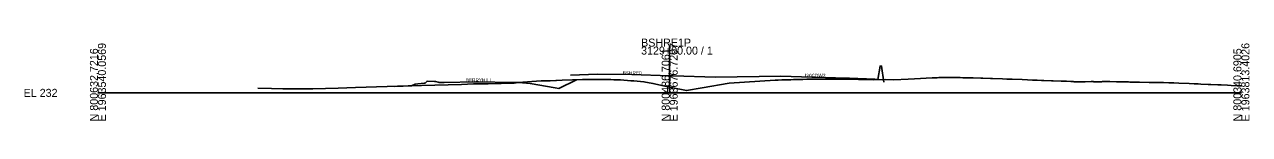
# Model space of a CAD drawing. Extents: x -26 to 403, y -10 to 6039.
# Drawn here: x -25.7 to 402.8, y 490.3 to 519 of the extents above; entities that cross this region are included whole.
import ezdxf

# ---------------------------------------------------------------- set-up
doc = ezdxf.new("R2010")
doc.units = 0
for name, color, linetype in [('Default', 7, 'Continuous'), ('RD_GPK_XS_Cell', 7, 'Continuous'), ('RD_TX_Misc1', 7, 'Continuous'), ('RD_XS_ExGround', 7, 'Continuous'), ('RD_XS_Pave', 7, 'Continuous'), ('RD_XS_TX_Elev_EX', 7, 'Continuous')]:
    doc.layers.add(name, color=color, linetype=linetype)

msp = doc.modelspace()

# ---------------------------------------------------------------- linework, layer by layer
at = {"layer": 'RD_GPK_XS_Cell'}
for p, q in [((200, 500), (200, 516.2)), ((0, 500), (200, 500)), ((200, 500), (400, 500))]:
    msp.add_line(p, q, dxfattribs=at)
at = {"layer": 'RD_XS_ExGround'}
msp.add_lwpolyline([(55.9, 501.67), (60.74, 501.51), (64.71, 501.39), (75.16, 501.41), (84.09, 501.66), (90.08, 501.85), (108.54, 502.41), (127.15, 502.96), (131.41, 503.12), (136.45, 503.18), (145.61, 503.42), (147.06, 503.59), (155.03, 504.18), (158.15, 504.26), (160.18, 504.38), (160.39, 504.38), (162.41, 504.45), (166.05, 504.54), (169.55, 504.62), (170.01, 504.62), (171.13, 504.64), (172.02, 504.64), (172.53, 504.64), (173.36, 504.64), (176.01, 504.64), (177.01, 504.64), (179.47, 504.62), (180.48, 504.61), (182, 504.58), (182.78, 504.52), (186.41, 504.24), (187.52, 504.15), (190.99, 503.87), (194.12, 503.28), (200, 502.03), (205.86, 500.78), (211.33, 501.73), (220.85, 503.39), (231.52, 504.07), (236.85, 504.43), (237.91, 504.47), (239.22, 504.52), (241.11, 504.57), (242.37, 504.61), (243.31, 504.64), (243.66, 504.65), (244.55, 504.67), (245.49, 504.7), (246.55, 504.72), (247.98, 504.76), (249.04, 504.79), (250.21, 504.81), (251.16, 504.82), (251.53, 504.83), (251.93, 504.82), (253.86, 504.81), (254.82, 504.81), (256.09, 504.8), (257.5, 504.8), (257.86, 504.79), (258.2, 504.79), (259.62, 504.79), (261.15, 504.77), (261.55, 504.77), (262.51, 504.77), (262.84, 504.76), (266.02, 504.64), (271.47, 504.57), (275.67, 504.63), (278.47, 504.54), (283.43, 504.83), (285.63, 504.95), (291.82, 505.27), (292.39, 505.3), (293.57, 505.31), (294.13, 505.39), (294.72, 505.4), (295.89, 505.4), (296.86, 505.4), (297.66, 505.39), (298.51, 505.38), (299.3, 505.37), (301.63, 505.33), (302.5, 505.31), (303.68, 505.31), (304.93, 505.28), (306.15, 505.25), (308.91, 505.17), (309.58, 505.15), (312.22, 505.04), (312.98, 505.01), (316.39, 504.89), (317.97, 504.83), (319.87, 504.76), (323.3, 504.63), (325.13, 504.55), (326.92, 504.47), (328.59, 504.42), (330.13, 504.37), (330.87, 504.35), (333.53, 504.25), (334.15, 504.23), (336.94, 504.12), (337.86, 504.09), (338.77, 504.06), (340.35, 503.97), (341.2, 503.92), (341.5, 503.88), (342.75, 503.83), (343.6, 503.84), (344.64, 503.86), (345.31, 503.89), (347.46, 503.97), (348.19, 503.92), (348.39, 503.91), (349.32, 503.89), (350.18, 503.88), (351.07, 503.87), (351.39, 503.95), (352.95, 503.96), (353.51, 503.97), (353.97, 503.96), (356.34, 503.89), (356.93, 503.88), (357.51, 503.86), (360.09, 503.81), (360.49, 503.8), (360.92, 503.79), (362.22, 503.76), (364.34, 503.7), (367.69, 503.65), (369.3, 503.63), (370.72, 503.6), (371.17, 503.59), (372.75, 503.57), (374.64, 503.53), (376.36, 503.49), (378.15, 503.42), (381.7, 503.28), (383.44, 503.2), (384.91, 503.13), (385.8, 503.09), (388.34, 502.96), (389.32, 502.91), (391.75, 502.81), (392.89, 502.76), (395.15, 502.66), (396.47, 502.6), (398.58, 502.5), (399.62, 502.45), (400, 502.43)], dxfattribs=at)
at = {"layer": 'RD_XS_Pave'}
for points in [[(165.26, 506.2), (174.81, 506.58), (186.81, 506.37), (200, 505.98), (201.28, 505.94), (216, 505.5), (238.85, 505.82)], [(238.85, 505.82), (249.68, 505.5), (250.86, 505.46), (261.61, 505.14), (262.87, 505.11), (271.77, 504.75), (272.87, 504.71), (273.62, 509.38), (274.12, 509.38), (274.87, 503.71)], [(103.9, 502.27), (109.74, 502.44), (110.98, 503.05), (111.93, 503.21), (114.07, 503.37), (114.5, 503.4), (115.13, 504.1), (117.75, 504.01), (118.14, 503.99), (119.01, 503.69), (119.39, 503.65), (121.15, 503.68), (132.15, 503.87), (133.18, 503.89), (144.66, 503.63), (145.22, 503.61), (147.22, 503.57), (151.24, 503.24), (159.94, 501.76), (161.27, 501.54), (167.37, 504.57)]]:
    msp.add_lwpolyline(points, dxfattribs=at)

# ---------------------------------------------------------------- texts
at = {"layer": 'Default'}
msp.add_text('-', height=0.0001, dxfattribs=at).set_placement((0, 500))
at = {"layer": 'RD_GPK_XS_Cell'}
for s, p in [('BSHRE1P', (190, 516.2)), ('3129+00.00 / 1', (190, 513.4)), ('EL 232', (-26, 498.6))]:
    msp.add_text(s, height=2.8, dxfattribs=at).set_placement(p)
for s, p in [('N 800632.7216', (0, 490)), ('E 1963540.0569', (2.8, 490)), ('N 800486.7061', (200, 490)), ('E 1963676.7297', (202.8, 490)), ('N 800340.6905', (400, 490)), ('E 1963813.4026', (402.8, 490))]:
    msp.add_text(s, height=2.8, rotation=90, dxfattribs=at).set_placement(p)
at = {"layer": 'RD_TX_Misc1'}
for s, p in [('BSHRE0', (183.58, 506.37)), ('I20CDW2', (247.34, 505.47)), ('BERRYHILL', (128.68, 503.88))]:
    msp.add_text(s, height=1.2, dxfattribs=at).set_placement(p)
at = {"layer": 'RD_XS_TX_Elev_EX'}
msp.add_text('234.03', height=1, dxfattribs=at).set_placement((197.9, 499.53))

doc.saveas('drawing.dxf')
